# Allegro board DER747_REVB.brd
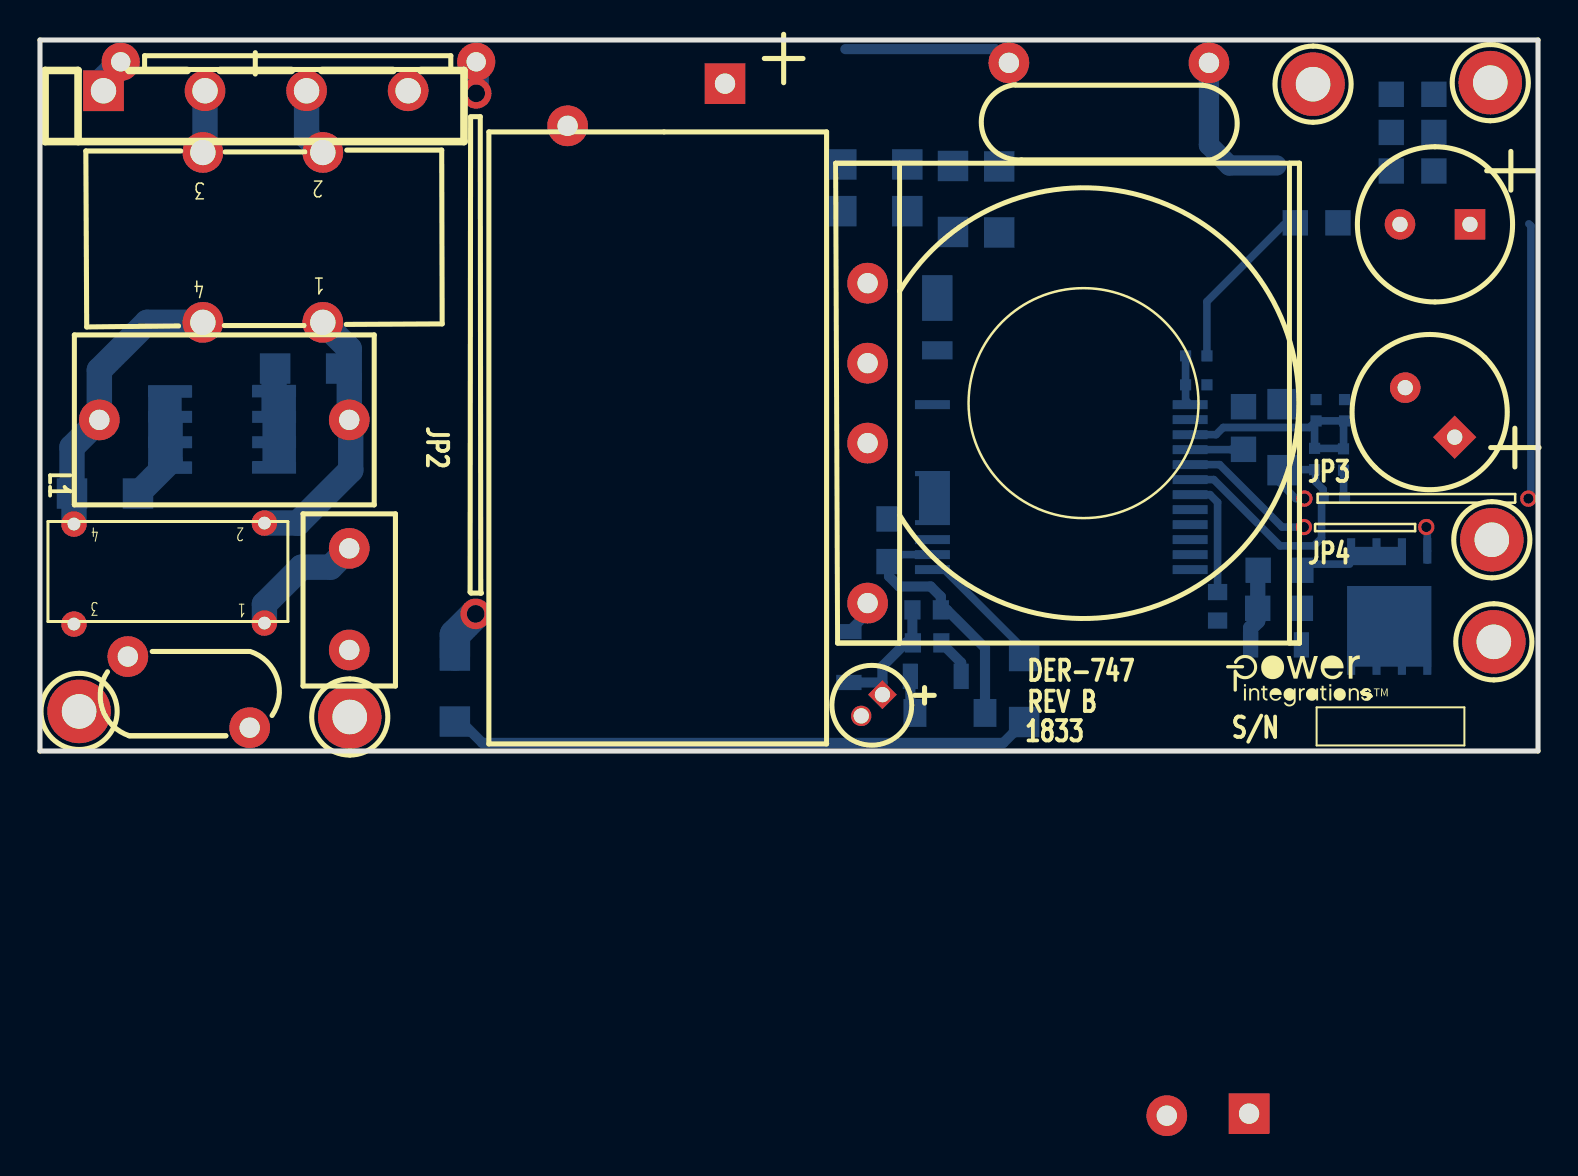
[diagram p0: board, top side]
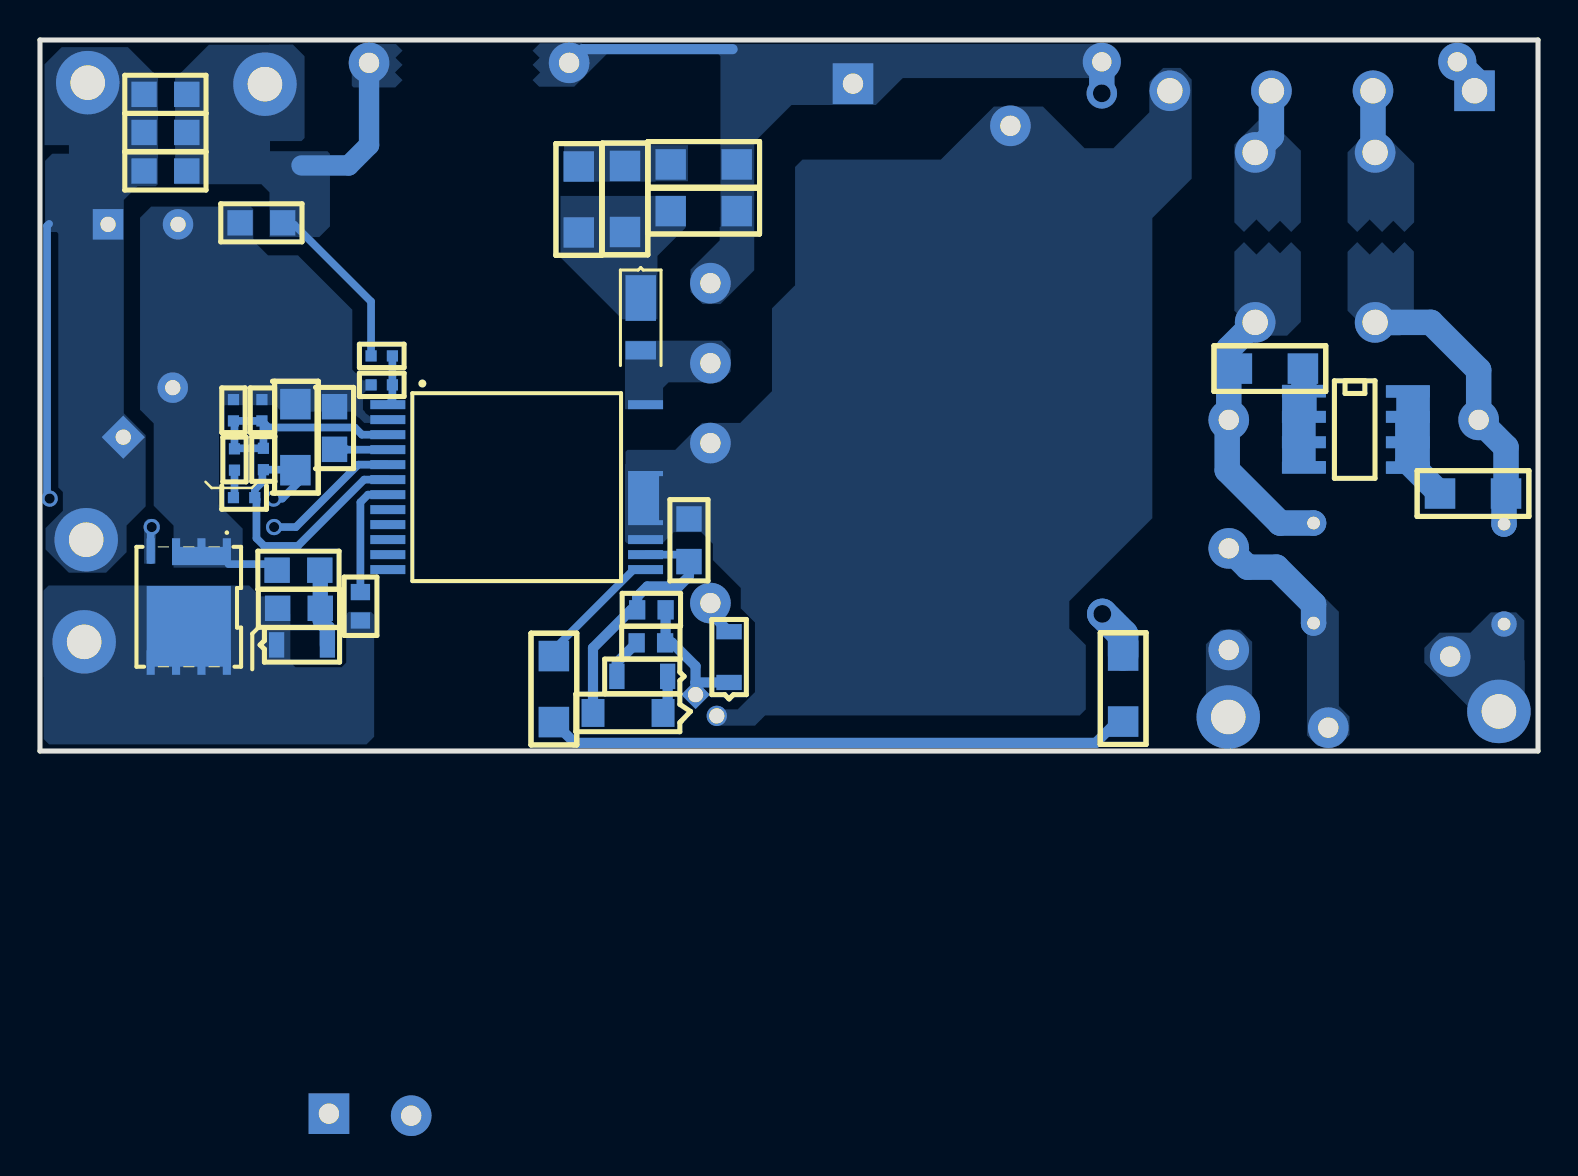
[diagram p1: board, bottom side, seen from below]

Outline 74.93 x 35.56 mm; copper layers: TOP, BOTTOM. Coordinates in mm from the lower left corner of the outline.
Outline path: 0,35.56 74.93,35.56 74.93,0 0,0 0,35.56

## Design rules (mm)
constraint set DEFAULT: min track width 0.508

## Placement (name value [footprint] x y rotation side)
BR1  GBL06  [PIDAXBRIDGEGBL06]  3.17 33.02 0 top
C1  330 nF  [PINP_XCAPRAD15X8P5X14HD040]  15.47 16.56 180 top
C2  100 uF  [PIPOLCAPCLYD630LS300040]  34.26 33.38 180 bottom
C3  470 pF  [PINPCAPRAD374X275LS394D030]  48.46 34.42 0 top
C4  2.2 nF  [PISMC1206]  40.08 29.34 0 bottom
C5  6.8 uF  [PIPOLCAP4P0X11P0XLS1P5D030]  42.14 2.82 225 top
C6  4.7 uF  [PISMC0805]  42.47 9.47 90 bottom
C7  1 nF  [PISMC0805]  60.93 9.04 0 bottom
C8  330 uF  [PIPOLCAPCYLD315LS138D030]  70.76 15.7 135 top
C9  330 uF  [PIPOLCAPCYLD315LS138D030]  71.53 26.34 180 top
C10  2.2 uF  [PISMC0805]  60.2 17.22 270 bottom
C11  2.2 uF  [PISMC1206]  62.15 17.35 270 bottom
C12  1000 pF  [PISMR0402]  58.37 18.31 180 bottom
C13  330 pF  [PISMC0402]  63.83 16.51 90 bottom
C14  330 pF  [PISMC0402]  65.2 14.05 90 bottom
C15  10 uF  [PISMC0805]  69.72 29.01 180 bottom
C16  1 uF  [PISMC0805]  69.72 30.94 180 bottom
C17  1 uF  [PISMC0805]  69.72 32.84 180 bottom
D1  DFLR1800-7  [PISMDDFLR120012]  44.88 22.68 90 bottom
D2  BAV3004WS-7  [PISMSOD323]  40.46 3.43 90 bottom
D3  BAV19WS  [PISMSOD323]  43.54 3.73 0 bottom
D4  BAV19WS  [PISMSOD323]  63.09 5.31 180 bottom
F1  3.15 A  [PI_RST_MICROFUSE]  15.47 5.05 90 top
FL1  Hole_70mils  [PI_HOLE_70MIL]  72.62 10.54 0 top
FL2  Hole_70mils  [PI_HOLE_70MIL]  72.72 5.44 0 top
J1  PCB Terminal 18 AWG  [PI_HOLE_18AWG]  15.49 1.68 0 top
J2  PCB Terminal 18 AWG  [PI_HOLE_18AWG]  1.96 1.96 0 top
J3  PCB Terminal 18 AWG  [PI_HOLE_18AWG]  72.54 33.4 0 top
J4  PCB Terminal 18 AWG  [PI_HOLE_18AWG]  63.68 33.32 0 top
JP1  J  [PI_JUMPER700]  4.04 34.47 0 top
L1  250 uH  [PI_TOROID_CMC4P_V_275UH]  7.9 6.48 180 top
L2  04291-T231  [PI_CMC_18MH_SUMIDA]  14.15 21.44 180 top
NOREF  -  []  58.78 4.7 0 top
NOREF#2  -  []  0.03 0.03 90 top
NOREF#3  -  []  0 35.56 0 top
NOREF#4  -  []  -153.38 54.28 0 top
NOREF#5  -  []  -231.19 -144.73 0 top
Q1  AONS62922  [PISMPQFN5X6B]  65.58 10.01 0 bottom
R1  1 M  [PISMR1206]  15.06 19.13 180 bottom
R2  1 M  [PISMR1206]  4.9 12.88 180 bottom
R3  2.00 M  [PISMR1206]  20.75 1.47 90 bottom
R4  1.80 M  [PISMR1206]  49.23 4.75 270 bottom
R5  20  [PISMR1206]  47.98 25.93 90 bottom
R6  20  [PISMR1206]  45.67 25.96 90 bottom
R7  680 k  [PISMR1206]  40.08 27 0 bottom
R8  3 k  [PISMR0603]  43.64 7.06 0 bottom
R9  47  [PISMR0603]  43.66 5.41 0 bottom
R11  10  [PISMR0805]  60.91 7.14 0 bottom
R12  47  [PISMR0603]  58.9 6.53 90 bottom
R13  1 k  [PISMR0402]  57.3 19.76 0 bottom
R14  0.009  [PISMR0805]  64.92 26.42 180 bottom
R15  169.0 k  [PISMR0402]  63.75 14.07 90 bottom
R16  11.5 k  [PISMR0402]  65.25 17.58 270 bottom
R17  1 k  [PISMR0402]  64.19 12.67 0 bottom
RV1  275 Vac  [PIDISC350X160LS210X140040]  10.49 1.17 180 top
T1  EQ25  [PI_BOBBIN_EQ-25_6P]  52.2 17.4 0 top
U1  InSOP24A  [PI_IC_INSOP_24D]  57.53 17.32 180 bottom
U2  CAP200DG  [PI_IC_SMD_SO8_CAPZERO]  11.71 17.98 270 bottom
VR1  MMSZ5242B-7-F  [PI_SM_SOD-123_12]  43.76 1.91 0 bottom

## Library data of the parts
BR1 = DISCRETE BRIDGE_+~~-: room: 1
C1 = CAP NP: alternate symbols: (pinp_xcaprad15x8p5x14Hd040H); room: 1
C2 = CAP POL: alternate symbols: (pipolcapclyd630ls3000401120h); room: 1
C3 C6 C11 C16 C17 = CAP NP: room: 2
C4 = CAP NP_0: room: 1
C5 = CAP POL: alternate symbols: (pipolcap4p0x11p0xls1p5d030h); room: 1
C7 C15 = CAP NP: alternate symbols: (pismc0805_1); room: 2
C8 C9 = CAP POL: alternate symbols: (pipolcapcyld315ls138d030h); room: 2
C10 = CAP NP_0: room: 2
C12-C14 = CAP NP: alternate symbols: (pismr0402_1); room: 2
D1-D3 = DIODE: room: 1
D4 = DIODE: room: 2
F1 = FUSE: alternate symbols: (pirstmicrofusehoz); room: 1
FL1 FL2 = FlyingLead: room: 2
J1 J2 = TERM_1Pin: room: 1
J3 J4 = TERM_1Pin: room: 2
JP1 = JUMPER_1
L1 = TORRID 4P_12_34: alternate symbols: (pi_toroid_CMC4p_V,pi_toroid_CMC4p_V_275uH); room: 1
L2 = TORRID 4P_12_43a: room: 1
Q1 = FET_N_SGD_123_4_5678: room: 2
R1-R9 = R: room: 1
R11 R12 R14-R16 = R: room: 2
R13 R17 = R: alternate symbols: (pismr0402_1); room: 2
RV1 = VARISTOR: alternate symbols: (pi_disc_354x220_ls220x10_040_h); room: 1
T1 = BEQ2506_6P
U1 = DEV_InSOP_0: room: 2
U2 = CAPZero: room: 1
VR1 = DIODE_ZENER: room: 1

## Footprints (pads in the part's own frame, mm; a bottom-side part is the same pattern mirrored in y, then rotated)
PI_BOBBIN_EQ-25_6P
  rect 2.032x2.032 hole 1.016: 1(8.28,-35.535)
  round 2.032 hole 1.016: 2(-10.8,5.999) 3(-10.8,1.999) 4(-10.8,-1.999) 5(4.166,-35.636) 6(-10.8,-10)
PI_CMC_18MH_SUMIDA
  round 2.032 hole 1.27: 1(0,0) 2(0,-8.499) 3(5.999,-8.499) 4(5.999,0)
PI_HOLE_18AWG
  round 3.175 hole 1.727: 1(0,0.025)
PI_HOLE_70MIL
  round 3.175 hole 1.727: 1(0,0.025)
PI_IC_INSOP_24D
  rect 1.75x0.45 smd: 1(0,0) 2(0,-0.749) 3(0,-1.501) 4(0,-2.25) 5(0,-3) 6(0,-3.749) 7(0,-4.501) 8(0,-5.25) 9(0,-5.999) 10(0,-6.749) 11(0,-7.501) 12(0,-8.25) 13(12.89,-8.25) 14(12.89,-7.501) 15(12.89,-6.749) 24(12.89,0)
  custom 0.437x0.437 smd: 16(12.89,-4.671)
PI_IC_SMD_SO8_CAPZERO
  rect 0.599x2.2 smd: 1(0,0) 2(1.27,0) 3(2.54,0) 4(3.81,0) 5(3.81,5.199) 6(2.54,5.199) 7(1.27,5.199) 8(0,5.199)
PI_JUMPER700
  round 1.905 hole 0.965: 1(0,0) 2(17.78,0)
PI_RST_MICROFUSE
  round 2.032 hole 1.016: 1(0,0) 2(5.08,0)
PI_SM_SOD-123_12
  rect 1.143x1.397 smd: 1(0,0) 2(3.505,0)
PI_TOROID_CMC4P_V_275UH
  round 1.27 hole 0.635: 1(-3.327,0.076) 2(-3.327,-4.925) 3(6.2,0.127) 4(6.2,-4.874)
PIDAXBRIDGEGBL06
  rect 2.032x2.032 hole 1.27: 1(0,0)
  round 2.032 hole 1.27: 2(5.08,0) 3(10.16,0) 4(15.24,0)
PIDISC350X160LS210X140040
  round 2.032 hole 1.016: 1(0,0) 2(6.096,-3.556)
PINP_XCAPRAD15X8P5X14HD040
  round 2.032 hole 1.016: 1(0,0) 2(12.499,0)
PINPCAPRAD374X275LS394D030
  round 2.032 hole 1.016: 1(0,0) 2(10.008,0)
PIPOLCAP4P0X11P0XLS1P5D030
  rect 1.016x1.016 hole 0.762: 1(0,0)
  round 1.016 hole 0.762: 2(1.501,0)
PIPOLCAPCLYD630LS300040
  rect 2.032x2.032 hole 1.016: 1(0,0)
  round 2.032 hole 1.016: 2(7.874,-2.108)
PIPOLCAPCYLD315LS138D030
  rect 1.524x1.524 hole 0.762: 1(0,0)
  round 1.524 hole 0.762: 2(3.5,0)
PISMC0402
  rect 0.559x0.559 smd: 1(0,0) 2(1.067,0)
PISMC0805
  rect 1.27x1.27 smd: 1(0,0) 2(2.134,0)
PISMC1206
  rect 1.524x1.524 smd: 1(0,0) 2(3.302,0)
PISMDDFLR120012
  rect 2.286x1.524 smd: 1(-0.025,0)
  rect 0.914x1.524 smd: 2(-2.642,0)
PISMPQFN5X6B
  rect 0.406x1.27 smd: 1(0,0) 2(1.27,0) 3(2.54,0) 4(3.81,0)
  rect 0.406x1.219 smd: 5(3.81,5.588) 6(2.54,5.588) 7(1.27,5.588) 8(0,5.588)
PISMR0402
  rect 0.559x0.559 smd: 1(0,0) 2(1.067,0)
PISMR0603
  rect 0.813x0.965 smd: 1(0,0) 2(1.422,0)
PISMR0805
  rect 1.27x1.27 smd: 1(0,0) 2(2.134,0)
PISMR1206
  rect 1.524x1.524 smd: 1(0,0) 2(3.302,0)
PISMSOD323
  rect 0.762x1.27 smd: 1(0,0) 2(2.54,0)

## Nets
GND: C7.2 C8.2 C9.2 C10.1 C11.1 C12.1 C13.2 Q1.1(S) Q1.2 Q1.3 R14.1 R16.1 U1.2
GND_SIGNAL: C3.2 C15.2 C16.2 C17.2 J4.1 R13.2 R14.2
VBUS_IN: C8.1 C9.1 C11.2 C15.1 C16.1 C17.1 FL1.1 J3.1 R15.1 R17.1 U1.6
D: D4.1 FL2.1 Q1.5 Q1.6 Q1.7 Q1.8 R11.2 R12.1
NC8: U1.8
NC9: U1.9
NC10: U1.10
NC11: U1.11
NC12: U1.12
V-PIN: R4.1 U1.13(VPIN)
N10479111: F1.1 J1.1
N10805923: BR1.4 C2.2 C5.2 C6.2 T1.4 U1.15 U1.16
N10806149: C6.1 R8.2 U1.14 VR1.2
N10808843: C12.2 R13.1 U1.1
N10809540: Q1.4 U1.5
N10813018: R3.1 R4.2
N10840366: C2.1 C3.1 C4.1 JP1.2 R3.2 R7.1 T1.2
N10869805: C10.2 U1.4
N10873526: R12.2 U1.7
N10897256: C13.1 C14.2 R15.2 R16.2 U1.3
N10950053: C5.1 D2.1 R8.1 R9.1
N10966650: D1.2 T1.3 U1.24
N11058959: BR1.1 JP1.1
N11077448: D3.2 R9.2
N11099981: C1.1 L1.2 L2.1 R1.1
N11100013: C1.2 L1.4 L2.4 R2.2
N11100021: BR1.3(AC2) L2.2
N11100037: BR1.2 L2.3
N11105885: D2.2 T1.6
N11108210: F1.2 L1.1 RV1.1
N11139529: D1.1 R5.1 R6.1 R7.2
N11139619: C4.2 R5.2 R6.2
N11156493: C7.1 D4.2 R11.1
N11376604: J2.1 L1.3 RV1.2
N11381159: R1.2 U2.2
N11381167: R2.1 U2.7
N11473834: D3.1 VR1.1
N11479585: C14.1 R17.2

Pads without a net: T1 1 5; U2 1 3 4 5 6 8

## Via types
v1: diameter 1.524, hole 0.889, TOP to BOTTOM, 2 vias
v2: diameter 0.813, hole 0.508, TOP to BOTTOM, 4 vias

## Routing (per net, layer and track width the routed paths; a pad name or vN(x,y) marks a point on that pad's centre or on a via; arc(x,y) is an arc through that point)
GND: length 3
  BOTTOM w0.381: C7.2 63.37,9.35 65.51,9.35 ; 62.26,17.22 62.15,17.32 C11.1 ; 59.99,17.35 60.12,17.22 C10.1
GND_SIGNAL: length 16.7
  BOTTOM w0.381: R13.2 58.37,22.48 62.2,26.31 62.69,26.31 R14.2
  BOTTOM w1.016: C3.2 58.47,30.3 59.49,29.29 61.85,29.29
VBUS_IN: length 29.6
  BOTTOM w0.381: U1.6 58.71,13.57 62.03,10.26 63.72,10.26 64.1,10.64 64.1,12.59 R17.1 64.19,13.08 63.8,13.46 63.8,14.02 R15.1 62.18,14.07 C11.2 62,13.89 62,13.44 62.81,12.62 v2(63.25,12.62) 63.25,12.45 ; v2(74.45,12.62) 74.57,12.75 74.57,26.26 74.47,26.37
V-PIN: length 6.6
  BOTTOM w0.381: R4.1 49.15,4.83 49.15,5.16 45.23,9.07 U1.13
N10806149: length 13
  BOTTOM w0.381: C6.1 42.82,9.82 U1.14
  BOTTOM w0.508: C6.1 42.47,8.74 42.98,8.23 44.55,8.23 45.06,7.72 R8.2 45.36,7.06 47.27,5.16 VR1.2
N10808843: length 2.5
  BOTTOM w0.381: U1.1 57.3,17.55 C12.2 R13.1
N10809540: length 8.7
  BOTTOM w0.381: v2(69.34,11.2) 69.39,11.15 Q1.4 69.39,9.55 ; v2(63.22,11.2) 62.13,11.2 59.01,14.32 U1.5
N10813018: length 29.4
  BOTTOM w0.508: R3.1 20.8,1.52 21.01,1.52 22.12,0.41 48.18,0.41 R4.2
N10840366: length 12.6
  BOTTOM w0.508: 40.28,35.1 47.78,35.1 C3.1
  BOTTOM w1.27: JP1.2 v1(21.82,32.89)
  BOTTOM w1.524: R3.2 20.75,5.82 v1(21.79,6.86)
N10869805: length 2.7
  BOTTOM w0.381: C10.2 59.59,15.09 59.57,15.07 U1.4
N10873526: length 6
  BOTTOM w0.381: R12.2 58.9,12.44 58.52,12.82 U1.7
N10897256: length 12.2
  BOTTOM w0.381: 63.75,16.43 C13.1 R16.2 65.2,16.46 C14.2 65.18,15.14 63.75,15.14 63.75,16.43 ; 63.75,16.43 63.5,16.18 59.18,16.18 58.83,15.82 U1.3
N10950053: length 6.8
  BOTTOM w0.508: R9.1 43.64,5.43 ; 43.64,5.43 43.33,5.43 42.14,4.24 42.14,3.43 ; 43.64,5.43 43.64,5.44 R8.1 ; D2.1 42.14,3.43 ; 42.14,3.43 C5.1
N11058959: length 1.8
  BOTTOM w1.27: JP1.1 3.17,33.6 BR1.1
N11077448: length 2.1
  BOTTOM w0.508: D3.2 46.08,4.42 R9.2
N11099981: length 14
  BOTTOM w1.27: L2.1 15.47,20.12 15.47,18.72 ; 15.47,18.72 R1.1 ; 15.47,18.72 C1.1 15.54,16.48 15.54,14.05 12.9,11.4 12.9,11.4 L1.2
N11100013: length 14.5
  BOTTOM w1.27: L1.4 1.7,12.78 R2.2 1.6,15.19 C1.2 2.97,19.05 5.36,21.44 L2.4
N11100021: length 3.4
  BOTTOM w1.27: BR1.3 13.33,30.75 L2.2
N11100037: length 3.1
  BOTTOM w1.27: BR1.2 8.25,30.04 L2.3
N11105885: length 1.8
  BOTTOM w0.508: D2.2 41.4,6.9 T1.6
N11108210: length 6.3
  BOTTOM w1.27: F1.2 14.53,9.19 13.08,9.19 11.23,7.34 L1.1
N11156493: length 3.9
  BOTTOM w0.762: D4.2 60.55,6.15 60.91,6.5 R11.1 60.91,9.02 C7.1
N11381159: length 2.4
  BOTTOM w1.27: R1.2 11.71,19.08 U2.2
N11381167: length 4.5
  BOTTOM w1.27: R2.1 6.51,14.49 U2.7
N11473834: length 1.9
  BOTTOM w0.508: VR1.1 43.54,2.13 D3.1
N11479585: length 1.4
  BOTTOM w0.381: C14.1 65.2,12.73 R17.2

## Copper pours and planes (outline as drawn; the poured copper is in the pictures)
GND on BOTTOM (solid shape): 68.33,9.3 65.41,9.3 65.41,10.21 68.33,10.21
GND on BOTTOM: 64.8,9.17 64.8,11.13 65.99,12.32 65.99,12.95 65.98,12.97 65.98,17.11 65.79,17.3 63.17,17.3 62.84,16.97 59.26,16.97 59.26,16.92 58.75,16.41 56.72,16.41 56.67,16.46 56.67,16.64 56.77,16.74 58.45,16.74 58.78,17.07 58.78,17.86 58.6,18.03 58.57,18.01 58.14,18.01 58.06,18.08 58.06,18.52 58.09,18.54 58.78,18.54 59.31,19.08 59.31,22.07 62.03,24.79 63.53,24.79 64.26,25.53 64.26,27.1 64.39,27.23 69.37,27.23 69.93,26.67 69.93,17.07 69.24,16.38 69.24,12.27 68.25,11.28 68.25,9.17
GND_SIGNAL on BOTTOM: 59.33,33.27 59.25,33.19 57.16,33.19 56.79,33.55 57.18,33.93 56.79,34.32 57.15,34.67 56.79,35.03 57.12,35.36 58.5,35.36 59.33,34.52
GND_SIGNAL on BOTTOM: 60.43,29.87 60.55,30 63.42,30 63.42,30.51 61.85,30.51 61.7,30.66 61.7,34.75 62.28,35.33 63.47,35.33 63.49,35.32 66.48,35.32 68.12,33.68 68.17,33.68 68.17,28.35 63.86,28.35 63.45,27.94 63.45,25.7 60.96,25.7 60.43,26.24
VBUS_IN on BOTTOM: 70.05,28.24 69.14,28.24 69.02,28.36 69.02,33.69 70.54,35.2 73.84,35.2 74.7,34.34 74.7,30.3 73.48,30.3 73.48,29.87 74.32,29.87 74.68,29.51 74.68,26.04 74.6,25.96 74.09,25.96 74.02,25.88 74.02,13.18 73.79,12.95 73.79,12.01 74.65,11.15 74.65,10.08 73.48,8.92 71.63,8.92 70.6,9.94 70.6,11.28 69.65,12.23 69.65,15.8 70.74,16.89 70.74,27.56
D on BOTTOM (solid shape): 69.6,4.22 65.38,4.22 65.38,8.25 69.6,8.25
D on BOTTOM: 74.75,3.71 74.74,3.7 74.74,0.6 74.47,0.33 58.6,0.33 58.22,0.71 58.22,6.53 58.23,6.54 58.23,6.82 58.37,6.96 59.49,6.96 59.61,6.83 59.61,4.42 59.82,4.22 59.82,4.19 62.15,4.19 62.41,4.45 62.41,6.83 62.42,6.85 62.42,7.73 63.92,7.73 64.47,8.28 74.5,8.28 74.75,8.03
Net_69 on BOTTOM (solid shape): 7.59,17.68 7.09,17.68 7.09,14.48 7.59,14.48 7.59,13.87 5.41,13.87 5.41,18.29 7.59,18.29
Net_73 on BOTTOM (solid shape): 12.8,13.89 10.62,13.89 10.62,14.5 11.13,14.5 11.13,17.7 10.62,17.7 10.62,18.31 12.8,18.31
N10479111 on BOTTOM: 16.61,0.79 16.18,0.36 14.83,0.36 14.3,0.89 14.3,5.46 14.91,6.07 15.88,6.07 16.61,5.33
N10805923 on BOTTOM: 29.87,29.58 27.22,32.23 24.77,32.23 22.68,30.15 21.23,30.15 19.44,31.94 19.44,33.46 18.75,34.16 17.88,34.16 17.5,33.78 17.5,33.76 17.32,33.58 17.32,28.63 19.29,26.66 19.29,11.65 23.44,7.49 23.44,6.12 22.62,5.3 22.62,2.08 22.92,1.78 38.66,1.78 39.17,1.27 41.22,1.27 41.55,1.6 41.55,1.85 41.33,2.08 40.03,2.08 39.17,2.95 39.17,6.43 39.88,7.14 39.88,8.15 41.27,9.55 41.27,10.36 41.86,10.95 43.23,10.95 43.79,10.39 45.57,10.39 45.67,10.49 45.67,14.35 45.64,14.35 45.64,14.96 45.54,15.06 43.15,15.06 41.81,16.41 39.9,16.41 38.32,18 38.32,22.14 37.16,23.29 37.16,29.21 36.79,29.58
N10809540 on BOTTOM: 69.14,9.37 69.14,10.62 69.13,10.63 69.13,10.83 68.96,11 68.96,11.4 69.16,11.61 69.55,11.61 69.72,11.43 69.72,9.37
N10840366 on BOTTOM: 21.62,35.36 40.89,35.36 41.15,35.1 41.15,35 40.89,34.75 40.89,26.24 40.93,26.2 40.93,25.54 42.39,24.08 42.39,22.96 41.78,22.35 40.89,22.35 39.2,24.04 39.2,30.44 37.34,32.31 33.12,32.31 31.78,33.66 21.62,33.66 21.25,34.02 21.26,34.04 21.26,35
N10840366 on BOTTOM: 47.78,35.33 47.84,35.39 49.92,35.39 50.29,35.03 49.94,34.67 50.29,34.32 49.91,33.93 50.29,33.55 49.96,33.22 48.21,33.22 46.3,35.13 46.23,35.13 46.43,35.33
N10966650 on BOTTOM: 43.76,17.09 43.76,18.16 43.48,18.44 40.92,18.44 40.39,18.97 40.39,20.07 40.84,20.52 45.67,20.52 45.67,17.09
N11099981 on BOTTOM: 13.46,25.45 12.9,24.89 12.34,25.45 11.86,24.97 11.86,21.46 12.55,20.78 13.94,20.78 15.19,22.02 15.19,24.97 14.71,25.45 14.08,24.83
N11100013 on BOTTOM: 7.8,25.45 7.24,24.89 6.68,25.45 6.21,24.98 6.21,21.45 6.88,20.78 8.28,20.78 9.52,22.02 9.52,24.97 9.04,25.45 8.42,24.83
N11100021 on BOTTOM: 12.9,26.52 13.46,25.96 14.07,26.57 14.07,26.59 14.71,25.96 15.19,26.44 15.19,30.33 13.84,31.67 13.51,31.67 11.86,30.02 11.86,26.44 12.34,25.96
N11100037 on BOTTOM: 7.24,26.52 7.8,25.96 8.41,26.57 8.41,26.59 9.04,25.96 9.52,26.44 9.52,29.95 8.84,30.63 7.44,30.63 6.2,29.39 6.2,26.44 6.68,25.96
N11108210 on BOTTOM: 9.43,0.81 9.98,0.25 11.02,0.25 11.56,0.79 11.56,5.87 11.84,6.15 11.84,7.72 11.66,7.9 10.9,7.9 9.96,6.96 9.96,2.25 9.43,1.72
N11139529 on BOTTOM: 48.89,27.76 48.89,24.69 45.8,21.59 44.04,21.59 44.04,24.77 42.65,26.16 42.65,27.79 42.66,27.8 42.7,27.76
N11139619 on BOTTOM: 42.52,30.3 42.52,28.5 44.12,28.5 44.15,28.47 48.72,28.47 48.72,30.3
N11376604 on BOTTOM: 0.66,1.12 0.66,4.52 0.69,4.55 0.69,6.53 1.09,6.93 2.36,6.93 3.38,5.92 4.93,5.92 5.69,5.16 5.69,4.42 1.93,0.66 1.12,0.66

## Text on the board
Ref Des/Silkscreen Top: 1833 | DER-747 | REV B | S/N | JP3 | JP4 | JP2
User.5: 14.  FAB HOUSE LOGO,DATE CODE TO BE IN SILK SCREEN ONLY.DO NOT USE COPPER. | 13.  MATERIAL FR4 COPPER 2oz THICKNESS 0.062" | PLEASE DELETE THESE PINS
User.8: FIGURE | FINISHED_SIZE | 20.0 | 25.0 | 30.0 | 35.0 | 38.0 | 40.0 | 50.0 | 68.0 | DRILL CHART: TOP to BOTTOM | ALL UNITS ARE IN MILS | TOLERANCE_DRILL | +0.0/-0.0 | +3.0/-3.0 | PLATED | QTY | 4 | 6 | 2 | 10 | 8
